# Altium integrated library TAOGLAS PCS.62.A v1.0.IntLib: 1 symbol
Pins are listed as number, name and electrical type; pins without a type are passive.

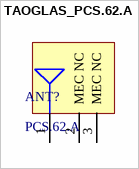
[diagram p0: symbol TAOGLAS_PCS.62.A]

## TAOGLAS_PCS.62.A
designator ANT?, comment PCS.62.A
Low Profile Wideband SMD Antenna 617-6000MHz 38*10*3mm; ComponentLibStatus: Created; MFG: Taoglas; Temp_High: +85C; Temp_Low: -40C
footprint TAOGLAS_PCS.62.A (Low Profile Wideband SMD Antenna 617-6000MHz 38*10*3mm)
pins: 1 RF Feed, 2 MEC NC, 3 MEC NC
